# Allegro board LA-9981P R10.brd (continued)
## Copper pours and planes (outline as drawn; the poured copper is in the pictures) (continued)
DH_CHG on TOP (solid shape): 152.62,169.75 152.62,168.79 152.49,168.67 151.48,168.67 151.29,168.86 151.29,169.81 151.41,169.94 152.43,169.94
DH_CHG on TOP (solid shape): 166.78,169.43 166.78,169.37 166.72,169.3 165.76,169.3 165.57,169.11 164.56,169.11 164.49,169.17 164.49,169.49 164.56,169.56 166.65,169.56
DH_CHG on IN1 (solid shape): 147.01,169.55 147.01,168.72 146.95,168.66 145.04,168.66 144.92,168.79 144.92,169.55 145.11,169.74 146.82,169.74
DH_CHG on IN1 (solid shape): 153.13,169.68 153.13,168.86 152.94,168.67 150.27,168.67 150.08,168.86 150.08,169.62 150.33,169.87 152.94,169.87
DH_CHG on IN1 (solid shape): 164.49,169.68 165.26,169.68 165.51,169.43 165.51,169.17 165.38,169.05 163.67,169.05 163.35,169.37 163.35,170 163.48,170.13 164.05,170.13
DL_1.35V on BOTTOM (solid shape): 157.58,12.72 157.58,11.83 157.45,11.71 156.56,11.71 156.44,11.83 156.44,12.66 156.56,12.79 157.52,12.79
DL_1.35V on BOTTOM (solid shape): 157.83,23.7 157.83,22.76 157.71,22.63 157.71,21.61 157.63,21.54 157.22,21.54 157.09,21.66 157.09,22.46 157.58,22.95 157.58,23.7 157.64,23.76 157.77,23.76
DL_1.35V on IN3 (solid shape): 157.58,12.98 157.58,11.77 157.48,11.67 156.53,11.67 156.44,11.77 156.44,13.04 156.63,13.23 157.32,13.23
DL_1.35V on IN3 (solid shape): 157.71,22.57 157.71,21.61 158.02,21.3 158.02,19.71 157.9,19.58 157.2,19.58 156.94,19.84 156.94,21.36 157.2,21.61 157.2,22.5 157.39,22.69 157.58,22.69
DL_CHG on TOP (solid shape): 161.83,175.52 161.83,174.89 161.57,174.64 160.18,174.64 159.99,174.45 159.16,174.45 158.97,174.64 158.97,175.46 159.16,175.65 161.7,175.65
DL_CHG on TOP (solid shape): 166.72,173.24 166.72,171.97 167.1,171.59 167.1,170.7 167.03,170.64 166.91,170.64 166.84,170.7 166.84,170.76 165.64,171.97 165.64,173.18 165.95,173.49 166.46,173.49
EN_PCIE on BOTTOM (solid shape): 197.23,66.3 197.23,65.75 197.48,65.5 198.16,65.5 198.26,65.4 198.26,64.76 198.17,64.67 196.55,64.67 196.16,65.07 195.57,65.07 195.51,65.13 195.51,66.23 195.67,66.39 197.15,66.39
ERP_LOT6 on TOP (solid shape): 129.07,174.15 129.07,172.9 129.88,172.09 129.88,170.78 129.81,170.71 129.27,170.71 129.22,170.77 129.22,172.13 128.67,172.68 128.67,174.17 128.76,174.26 128.97,174.26
GPU_B+ on TOP (solid shape): 214.26,79.73 214.26,74.86 213.64,74.24 213.64,64.78 213.07,64.21 207.62,64.21 207.62,64.22 207.35,64.22 207.27,64.3 207.27,76.05 211.2,79.98 214.02,79.98
INT-SPK-L+ on TOP (solid shape): 63.47,25.28 63.47,24.52 63.34,24.39 60.61,24.39 60.48,24.52 60.48,25.22 60.67,25.41 63.34,25.41
INT-SPK-L+ on TOP (solid shape): 27.08,16.01 27.08,15.82 26.38,15.12 26.19,15.12 26.06,15.25 26.06,15.63 26.64,16.2 26.89,16.2
INT-SPK-L+ on IN1 (solid shape): 62.7,25.03 62.7,24.39 62.45,24.14 60.42,24.14 60.23,24.33 60.23,25.16 60.29,25.22 62.51,25.22
INT-SPK-L+ on IN1 (solid shape): 27.97,17.54 27.97,16.65 26.44,15.12 26.25,15.12 26.06,15.31 26.06,15.63 26.83,16.39 26.83,16.44 26.84,16.45 26.92,16.69 26.83,16.92 26.83,17.28 27.14,17.6 27.91,17.6
INT-SPK-L- on TOP (solid shape): 63.47,24.08 63.47,23.25 63.4,23.19 60.73,23.19 60.48,23.44 60.48,24.01 60.73,24.27 63.27,24.27
INT-SPK-L- on TOP (solid shape): 27.45,15.96 27.45,15.3 26.89,14.74 26.7,14.74 26.57,14.87 26.57,15.11 26.61,15.16 26.94,15.5 26.97,15.52 27.14,15.7 27.14,15.71 27.21,15.77 27.21,15.95 27.27,16.01 27.4,16.01
INT-SPK-L- on IN1 (solid shape): 62.64,23.82 62.64,23.12 62.51,23 60.67,23 60.48,23.19 60.48,23.82 60.67,24.01 62.45,24.01
INT-SPK-L- on IN1 (solid shape): 29.49,16.77 29.49,16.2 29.21,15.92 29.13,15.89 29.05,15.94 28.7,16.11 28.41,15.86 28.4,15.82 28.35,15.82 27.88,15.35 27.86,15.35 27.58,15.25 27.48,14.97 27.48,14.95 27.14,14.62 26.76,14.62 26.57,14.81 26.57,15.06 28.67,17.15 29.11,17.15
INT-SPK-R+ on TOP (solid shape): 64.42,22.36 64.42,21.54 64.35,21.47 62,21.47 61.81,21.66 61.81,22.3 62,22.49 64.29,22.49
INT-SPK-R+ on IN1 (solid shape): 30.25,15.12 30.25,14.36 30.06,14.17 28.86,14.17 28.29,14.74 28.29,15.25 28.35,15.31 30.06,15.31
INT-SPK-R+ on IN1 (solid shape): 63.53,22.17 63.53,21.54 63.34,21.35 59.85,21.35 59.72,21.47 59.72,22.24 59.91,22.43 63.27,22.43
INT-SPK-R- on TOP (solid shape): 64.42,21.09 64.42,20.27 64.35,20.2 61.88,20.2 61.75,20.33 61.75,21.09 61.88,21.22 64.29,21.22
INT-SPK-R- on IN1 (solid shape): 63.53,21.16 63.53,20.33 63.4,20.2 59.91,20.2 59.72,20.39 59.72,20.97 59.97,21.22 63.47,21.22
INT-SPK-R- on IN1 (solid shape): 28.13,15.09 28.13,15.06 28.12,14.95 28.15,14.85 28.16,14.84 28.16,14.62 28.73,14.04 28.73,13.54 28.67,13.47 27.84,13.47 27.52,13.79 27.52,14.82 27.9,15.19 28.03,15.19
LDO_3V on BOTTOM (solid shape): 147.35,155.2 146.69,155.2 146.64,155.25 146.01,155.25 145.96,155.3 145.39,155.3 145.34,155.35 145.34,155.5 145.39,155.55 146,155.55 146.21,155.77 146.38,155.77 146.69,156.09 147.35,156.09
LG_3V on TOP (solid shape): 130.84,22.71 130.84,21.73 130.58,21.47 129.89,21.47 129.7,21.66 129.7,22.71 129.89,22.9 130.65,22.9
LG_3V on TOP (solid shape): 130,19.37 130,19.07 129.65,18.72 129.64,18.72 128.74,17.82 128.74,17.19 128.68,17.12 128.62,17.12 128.55,17.19 128.55,18.48 129.57,19.5 129.87,19.5
LG_5V on TOP (solid shape): 125.57,25.57 125.57,25.19 125.06,24.68 124.3,24.68 124.17,24.81 124.17,25 124.43,25.25 124.43,25.57 124.62,25.76 125.38,25.76
LG_5V on TOP (solid shape): 126.01,19.04 126.03,19.04 126.05,19.02 126.09,18.98 126.15,18.95 126.93,18.18 126.94,18.19 127.04,18.19 127.16,18.07 127.16,17.25 127.03,17.12 126.97,17.12 126.9,17.19 126.9,17.57 126.51,17.96 126.18,17.96 125.63,18.51 125.63,18.94 125.73,19.04
LG_5V on IN3 (solid shape): 126.63,18.39 126.63,17.99 126.49,17.85 126.2,17.85 124.99,19.06 124.99,19.27 125.37,19.65
LG_5V on IN3 (solid shape): 125.7,25.57 125.7,24.7 125.02,24.02 124.37,24.02 124.11,24.28 124.11,25.63 124.23,25.76 125.5,25.76
LG_+1.2VSP on BOTTOM (solid shape): 180.88,172.79 180.88,172.1 180.69,171.91 179.8,171.91 179.67,172.03 179.67,172.86 179.8,172.98 180.69,172.98
LG_+1.2VSP on IN3 (solid shape): 180.81,172.98 180.81,172.03 180.69,171.91 179.92,171.91 179.73,172.1 179.73,172.92 179.86,173.05 180.75,173.05
LG_+1.2VSP on IN3 (solid shape): 185.83,174.32 185.83,173.68 185.7,173.56 184.81,173.56 184.69,173.68 184.69,174.7 184.81,174.83 185.32,174.83
LX_1.05V on BOTTOM (solid shape): 147.67,159.01 147.67,157.74 147.55,157.61 146.66,157.61 146.53,157.74 146.53,159.01 146.66,159.13 147.55,159.13
LX_1.05V on BOTTOM (solid shape): 144.59,152.94 144.99,152.53 145.32,152.53 145.89,151.96 145.89,148.02 145.39,147.51 142.32,147.51 140.74,145.93 138.85,145.93 138.72,146.06 138.72,147.02 139.09,147.39 139.79,147.39 141.07,148.67 141.07,150.62 143.42,152.97 143.42,154.17 144.59,154.17
LX_1.5VSP on BOTTOM (solid shape): 110.12,29 110.12,26.97 109.99,26.84 109.99,26.08 109.93,26.01 109.8,26.01 109.74,26.08 109.74,26.78 109.55,26.97 108.85,26.97 108.66,26.78 108.66,26.52 108.02,26.52 108.02,27.41 107.77,27.66 105.77,27.66 105.35,28.08 105.35,29.76 105.61,30.01 109.1,30.01
LX_1.8VSP on BOTTOM (solid shape): 221.58,95.2 221.58,94.05 221.39,93.86 219.93,93.86 219.17,93.1 219.17,92.09 219.04,91.96 218.98,91.96 218.91,92.02 218.91,93.04 218.09,93.86 217.26,93.86 216.5,94.63 215.67,94.63 215.61,94.69 215.61,95.39 215.67,95.45 221.33,95.45
LX_3V on TOP (solid shape): 135.79,27.89 135.79,23.63 135.47,23.32 134.14,23.32 133.63,22.81 133.63,22.58 133.51,22.46 131.41,22.46 131.22,22.65 131.22,24.9 131.54,25.22 132.11,25.22 132.62,25.73 132.62,27.95 132.81,28.14 135.54,28.14
LX_3V on TOP (solid shape): 131.16,16.23 131.66,16.23 131.85,16.04 131.85,15.53 131.79,15.47 131.22,15.47 130.84,15.85 130.01,15.85 129.82,16.04 128.87,16.04 128.81,16.11 128.81,16.17 128.87,16.23 130.01,16.23 130.14,16.36 131.03,16.36
LX_3V on BOTTOM (solid shape): 135.79,27.73 135.79,23.47 135.41,23.09 130.52,23.09 130.33,23.28 130.33,27.73 130.58,27.98 135.54,27.98
LX_3V on IN1 (solid shape): 134.97,24.14 134.97,22.93 134.78,22.74 134.14,22.74 133.95,22.93 133.95,24.14 134.01,24.2 134.9,24.2
LX_3V on IN1 (solid shape): 131.92,16.71 131.92,16.42 131.35,15.85 130.14,15.85 130.01,15.98 130.01,16.33 130.36,16.68 131.09,16.68 131.38,16.97 131.66,16.97
LX_5V on TOP (solid shape): 125.66,16.2 126.58,16.2 126.65,16.14 126.65,16.03 126.58,15.96 125.55,15.96 125.44,15.85 124.65,15.85 124.43,16.08 123.89,16.08 123.77,16.2 123.77,16.69 123.85,16.77 125.09,16.77
LX_5V on TOP (solid shape): 122.27,28.74 122.27,27.25 122.2,27.19 120.78,27.19 120.49,26.9 120.49,25.88 120.68,25.69 121.95,25.69 122.54,25.11 123.58,25.11 123.66,25.03 123.66,22.65 123.47,22.46 121.25,22.46 121.12,22.58 121.12,23.09 120.87,23.34 119.22,23.34 119.03,23.54 119.03,28.62 119.35,28.93 122.08,28.93
LX_5V on BOTTOM (solid shape): outline of 85 points within 119.2,23.47 124.3,28.36
LX_5V on IN1 (solid shape): 125.7,16.61 125.7,15.79 125.5,15.6 123.41,15.6 123.16,15.85 123.16,16.74 123.28,16.87 125.44,16.87
LX_5V on IN1 (solid shape): 120.49,24.08 120.49,23.76 120.3,23.57 120.3,22.93 119.54,22.93 119.54,23.57 119.35,23.76 119.35,24.08 119.47,24.2 120.36,24.2
LX_CHG on TOP (solid shape): 166.78,168.98 166.78,168.86 166.72,168.79 165.76,168.79 164.87,167.9 163.6,167.9 163.54,167.97 163.54,168.73 163.6,168.79 164.56,168.79 164.68,168.92 165.57,168.92 165.7,169.05 166.72,169.05
LX_CHG on TOP (solid shape): 154.44,176.75 154.44,175.61 154.98,175.07 158.05,175.07 158.08,175.03 158.08,170.89 158.02,170.83 156.87,170.83 156.43,170.38 156.43,168.86 156.24,168.67 154.33,168.67 154.14,168.48 154.14,168.16 154.02,168.03 153.25,168.03 153.06,168.22 153.06,169.87 152.62,170.32 151.22,170.32 150.84,169.94 150.84,168.79 150.62,168.57 147.06,168.57 146.89,168.74 146.89,170.87 148.9,172.89 149.35,172.89 153.32,176.86 154.33,176.86
LX_CHG on BOTTOM (solid shape): 157.51,174.45 157.51,168.6 156.81,167.9 153.06,167.9 152.75,168.22 152.75,169.75 152.3,170.19 149.06,170.19 148.75,170.51 148.75,172.98 150.52,174.76 157.19,174.76
LX_CHG on IN1 (solid shape): 155.67,168.73 155.67,168.03 155.48,167.84 153.25,167.84 153.06,168.03 153.06,168.54 153.38,168.86 155.54,168.86
LX_CHG on IN1 (solid shape): 165.51,168.79 165.51,168.41 164.94,167.84 163.48,167.84 163.29,168.03 163.29,168.67 163.48,168.86 164.56,168.86 164.62,168.92 165.38,168.92
LX_PCIE on TOP (solid shape): 197.77,69.42 197.77,67.89 197.6,67.72 195.72,67.72 195.41,67.42 195.41,64.94 195.27,64.79 193.09,64.79 193.09,64.79 192.77,65.11 192.77,69.45 192.91,69.59 197.6,69.59
LX_PCIE on BOTTOM (solid shape): 197.85,69.83 197.85,67.06 197.6,66.81 195.53,66.81 194.81,66.08 194.81,65.19 194.72,65.11 193.08,65.11 192.84,65.35 192.84,69.88 193.24,70.29 197.39,70.29
LX_VDDCI on BOTTOM (solid shape): 185.89,184.1 185.89,175.91 185.77,175.78 184.5,175.78 184.12,176.16 184.12,177.37 182.16,179.32 182.16,180.4 181.19,181.37 179.86,181.37 179.73,181.49 179.73,182.45 179.8,182.51 181,182.51 183.23,184.73 185.26,184.73
MIC_IN on TOP (solid shape): 16.16,23.63 16.16,21.28 16.09,21.22 15.08,21.22 15.01,21.28 15.01,23.44 15.27,23.7 16.09,23.7
MIC_IN on TOP (solid shape): 27.52,25.28 27.52,24.46 27.4,24.33 27.4,23.19 27.33,23.12 27.21,23.12 27.14,23.19 27.14,24.27 27.02,24.39 27.02,24.65 27.14,24.78 27.14,25.22 27.27,25.35 27.46,25.35
MIC_IN on BOTTOM (solid shape): 16.48,22.49 16.48,21.85 16.41,21.79 15.27,21.79 15.01,22.05 15.01,22.87 15.08,22.93 16.03,22.93
MIC_IN on IN1 (solid shape): 16.03,24.14 16.03,22.68 15.9,22.55 15.14,22.55 15.01,22.68 15.01,24.08 15.21,24.27 15.9,24.27
MIC_IN on IN1 (solid shape): 27.52,25.22 27.52,24.46 27.33,24.27 26.06,24.27 25.94,24.39 25.94,25.22 26.13,25.41 27.33,25.41
MIC_IN_R on TOP (solid shape): 16.22,20.71 16.22,19.7 16.4,19.51 16.4,17.86 16.59,17.67 16.59,16.26 16.12,15.78 15.19,15.78 14.95,16.01 14.95,17.66 15.59,18.3 15.59,19.51 15.4,19.7 15.08,19.7 14.95,19.82 14.95,20.71 15.08,20.84 16.09,20.84
MIC_IN_R on IN3 (solid shape): 16.73,17.66 16.73,16.9 16.54,16.71 15.14,16.71 14.89,16.97 14.89,17.6 15.14,17.85 16.54,17.85
PCIE_B+ on BOTTOM (solid shape): 194.85,62.81 194.85,61.99 195.67,61.16 195.67,58.68 195.56,58.57 193.69,58.57 193.58,58.68 193.58,59.07 194.02,59.51 194.02,61.54 193.51,62.05 193.51,62.88 193.58,62.94 194.72,62.94
PSID on BOTTOM (solid shape): 138.38,183.06 138.38,178.15 138.11,177.89 135.72,177.89 135.36,178.24 135.36,183.19 135.46,183.29 138.15,183.29
REGN on TOP (solid shape): 165.19,172.92 165.19,171.52 166.14,170.57 166.65,170.57 166.78,170.44 166.78,170.38 166.65,170.25 165.76,170.25 165.51,170.51 164.3,170.51 164.18,170.64 164.18,171.46 164.37,171.65 164.37,173.05 164.43,173.11 165,173.11
RING2 on TOP (solid shape): 17.81,23.44 17.81,21.47 17.62,21.28 16.54,21.28 16.48,21.35 16.48,23.57 16.6,23.7 17.55,23.7
RING2 on TOP (solid shape): 28.22,25.28 28.22,24.39 28.16,24.33 28.03,24.33 27.84,24.14 27.84,23.19 27.78,23.12 27.65,23.12 27.59,23.19 27.59,24.2 27.78,24.39 27.78,25.28 27.84,25.35 28.16,25.35
RING2 on IN3 (solid shape): 17.68,23.76 17.68,22.62 17.55,22.49 16.86,22.49 16.6,22.74 16.6,23.82 16.79,24.01 17.43,24.01
RING2 on IN3 (solid shape): 28.29,26.24 28.29,24.33 28.16,24.2 27.84,24.2 27.71,24.33 27.71,25.35 27.59,25.47 26.89,25.47 26.83,25.54 26.83,26.17 27.08,26.43 28.1,26.43
RING2_R on TOP (solid shape): 17.68,20.71 17.68,19.77 17.48,19.57 17.48,18.43 18.28,17.64 18.28,15.4 18.04,15.16 17.06,15.16 16.89,15.34 16.89,17.95 16.66,18.17 16.66,19.7 16.54,19.82 16.54,20.71 16.6,20.78 17.61,20.78
RING2_R on IN3 (solid shape): 18.08,15.46 18.08,13.94 17.88,13.75 17.06,13.75 16.81,14 16.81,15.4 17.12,15.71 17.82,15.71
SNB_1.05V on BOTTOM (solid shape): 139.67,149.99 139.93,149.74 140.37,149.74 140.37,148.72 138.72,148.72 138.65,148.79 138.65,150.68 138.78,150.81 139.67,150.81
SNB_VDDCI on BOTTOM (solid shape): 183.04,177.56 183.04,175.84 182.97,175.78 180.75,175.78 180.62,175.91 180.62,176.54 180.69,176.6 181.7,176.6 181.83,176.73 181.83,177.56 181.89,177.62 182.97,177.62
SNUB_PCIE on TOP (solid shape): 197.96,66.74 197.96,64.81 197.85,64.7 196.86,64.7 196.78,64.79 196.78,65.5 196.71,65.57 195.96,65.57 195.75,65.77 195.75,66.83 195.87,66.96 197.74,66.96
SW_1.35V on TOP (solid shape): 154.66,16.85 154.66,15.64 154.72,15.58 154.72,15.33 154.59,15.2 153.77,15.2 153.58,15.39 153.58,16.79 153.77,16.98 154.53,16.98
SW_1.35V on TOP (solid shape): 157.39,23.65 157.39,23.39 156.37,22.38 156.05,22.38 155.74,22.69 155.74,23.14 156.44,23.84 157.2,23.84
SW_1.35V on BOTTOM (solid shape): 157.39,24.08 157.39,23.39 156.82,22.82 156.82,21.36 156.56,21.11 156.05,21.11 155.93,21.23 155.93,23.33 156.47,23.87 156.47,24.06 156.56,24.15 157.32,24.15
SW_1.35V on BOTTOM (solid shape): 155.16,17.73 155.16,15.32 155.93,14.55 155.93,11.69 156.05,11.57 156.56,11.57 156.68,11.44 156.68,10.93 156.62,10.87 154.1,10.87 152.37,12.6 150.34,12.6 149.96,12.98 149.96,16.6 150.72,17.36 153.07,17.36 153.5,17.79 153.51,17.79 153.57,17.85 155.03,17.85
SW_+1.2VSP on TOP (solid shape): 176.88,172.73 176.88,171.46 177.07,171.27 177.59,171.27 178.2,171.27 179.42,171.27 179.48,171.21 179.48,170.37 179.38,170.27 179.09,170.27 178.84,170.03 178.84,167.82 178.68,167.65 175.67,167.65 175.1,168.22 175.1,172.67 175.23,172.79 176.81,172.79
SW_+1.2VSP on TOP (solid shape): 185.7,172.35 185.7,172.22 185.64,172.16 184.81,172.16 184.69,172.03 184.44,172.03 184.38,171.97 184.37,171.97 184.12,171.72 183.87,171.72 183.8,171.71 183.67,171.59 183.67,171.4 183.54,171.27 182.72,171.27 182.65,171.33 182.65,171.91 183.16,172.41 185.64,172.41
SW_+1.2VSP on BOTTOM (solid shape): 179.42,175.02 179.42,168.03 179.1,167.71 175.16,167.71 174.78,168.1 174.78,172.22 177.66,172.22 177.67,172.16 177.68,172.11 177.7,172.06 177.73,172.02 177.77,171.96 177.77,171.93 177.77,171.9 177.73,171.84 177.7,171.8 177.68,171.75 177.67,171.7 177.66,171.64 177.67,171.59 177.68,171.54 177.7,171.49 177.72,171.44 177.76,171.4 177.8,171.36 177.84,171.33 177.89,171.31 177.94,171.29 177.99,171.28 178.05,171.28 178.1,171.29 178.15,171.31 178.2,171.33 178.24,171.36 178.28,171.4 178.32,171.44 178.34,171.49 178.36,171.54 178.37,171.59 178.38,171.64 178.37,171.7 178.36,171.75 178.34,171.8 178.31,171.84 178.27,171.9 178.27,171.93 178.27,171.96 178.31,172.02 178.34,172.06 178.36,172.11 178.37,172.16 178.38,172.22 178.37,172.27 178.36,172.32 178.34,172.37 178.32,172.42 178.28,172.46 178.24,172.5 178.2,172.53 178.15,172.55 178.1,172.57 178.05,172.58 177.99,172.58 177.94,172.57 177.89,172.55 177.84,172.53 177.8,172.5 177.76,172.46 177.72,172.42 177.7,172.37 177.68,172.32 177.67,172.27 177.66,172.22 174.78,172.22 174.78,175.21 174.97,175.4 179.04,175.4
SW_+1.2VSP on IN1 (solid shape): 179.73,171.02 180.56,171.02 180.69,170.89 180.69,170.44 180.5,170.25 179.23,170.25 179.04,170.44 179.04,171.14 179.23,171.33 179.42,171.33
SW_+1.2VSP on IN1 (solid shape): 184.75,172.35 184.75,172.1 184.63,171.97 184.6,171.98 184.53,171.98 184.45,171.97 184.13,171.97 183.99,171.97 183.35,171.33 182.91,171.33 182.78,171.46 182.78,171.84 183.42,172.48 184.62,172.48
SW_CPU2 on BOTTOM (solid shape): 112.36,143.19 112.36,140.71 112.34,140.7 110.93,140.7 110.65,140.41 110.65,139.2 110.46,139.01 109.38,139.01 109.19,138.82 109.19,138.19 109.12,138.12 106.26,138.12 106.2,138.19 106.2,139.52 106.39,139.71 108.3,139.71 108.42,139.84 108.42,140.54 108.36,140.6 106.52,140.6 106.14,140.98 106.14,142.82 106.65,143.33 112.22,143.33
SW_VGA_CORE on TOP (solid shape): 206.66,76.97 206.66,76.12 206.4,75.87 206.4,72.76 206.11,72.46 203.48,72.46 203.17,72.15 203.17,70.69 203.42,70.43 206.08,70.43 206.47,70.05 206.47,66.94 206.46,66.94 206.46,66.74 206.25,66.53 203.32,66.53 202.09,67.77 202.09,77.16 202.25,77.32 206.31,77.32
SW_VGA_CORE on BOTTOM (solid shape): 204.56,61.86 204.56,60.8 204.49,60.58 204.56,60.36 204.56,60.08 204.69,59.95 204.69,58.88 204.63,58.81 204.56,58.81 204.44,58.94 204.44,59.88 204.44,59.89 204.24,60.08 204.18,60.08 204.05,60.21 204.05,60.9 204.05,61.03 203.86,61.22 203.55,61.22 203.48,61.29 203.48,62.05 203.55,62.11 204.31,62.11
SW_VGA_CORE on BOTTOM (solid shape): outline of 156 points within 202.09,61.16 213.72,76.99
SW_VGA_CORE on IN1 (solid shape): 205.45,62.75 205.45,62.43 204.63,61.61 204.63,60.21 204.44,60.02 204.12,60.02 204.05,60.08 204.05,62.69 204.31,62.94 205.26,62.94
SW_VGA_CORE on IN1 (solid shape): 206.85,77.04 206.85,75.89 206.28,75.32 206.28,66.94 206.02,66.69 203.36,66.69 202.97,67.07 202.97,70.31 203.1,70.43 205.2,70.43 205.39,70.62 205.39,72.08 205.07,72.4 202.34,72.4 202.09,72.65 202.09,76.46 203.1,77.48 206.4,77.48
SW_VGA_CORE on IN2 (solid shape): 206.85,77.04 206.85,75.89 206.28,75.32 206.28,66.94 206.02,66.69 203.23,66.69 202.97,66.94 202.97,70.24 203.17,70.43 205.2,70.43 205.39,70.62 205.39,72.08 205.07,72.4 202.28,72.4 202.09,72.59 202.09,76.46 203.1,77.48 206.4,77.48
SW_VGA_CORE on IN3 (solid shape): 206.85,77.04 206.85,75.89 206.28,75.32 206.28,66.94 206.02,66.69 203.17,66.69 202.85,67 202.85,70.18 203.1,70.43 205.2,70.43 205.39,70.62 205.39,72.08 205.07,72.4 202.34,72.4 202.09,72.65 202.09,76.46 203.1,77.48 206.4,77.48
UG_3V on TOP (solid shape): 133.7,29.22 133.7,28.52 133.51,28.33 132.74,28.33 132.55,28.52 132.55,29.25 132.65,29.35 133.57,29.35
UG_3V on TOP (solid shape): 130.2,18.07 130.2,17.82 129.82,17.44 129.82,16.93 129.76,16.87 128.87,16.87 128.87,16.99 128.87,17.13 128.87,17.57 129.66,18.35 129.92,18.35
UG_3V on IN1 (solid shape): 131.09,18.66 131.09,18.54 129.68,17.12 129.07,17.12 128.93,17.26 128.93,17.53 130.5,19.09 130.66,19.09
UG_3V on IN1 (solid shape): 133.66,29.25 133.66,27.86 133.47,27.66 132.84,27.66 132.59,27.92 132.59,29.25 132.71,29.38 133.54,29.38
UG_5V on TOP (solid shape): 126.77,17.44 126.77,16.9 126.65,16.77 125.89,16.77 125.44,17.22 125.44,17.54 125.62,17.71 126.5,17.71
UG_5V on TOP (solid shape): 122.33,26.87 122.33,26.05 122.11,25.82 120.74,25.82 120.62,25.95 120.62,26.84 120.74,26.96 122.24,26.96
UG_5V on IN1 (solid shape): 125.76,17.69 126.65,17.69 126.71,17.63 126.71,17.31 126.46,17.06 124.81,17.06 124.64,17.22 124.64,17.66 124.88,17.9 125.55,17.9
UG_5V on IN1 (solid shape): 121.31,26.9 121.31,26.08 121.89,25.5 121.89,25.25 121.76,25.12 121.19,25.12 120.49,25.82 120.49,26.9 120.62,27.03 121.19,27.03
UG_+1.2VSP on TOP (solid shape): 178.27,172.35 178.27,171.52 178.15,171.4 177.64,171.4 177.13,171.91 177.13,172.6 177.26,172.73 177.89,172.73
UG_+1.2VSP on TOP (solid shape): 185.77,171.84 185.77,171.71 185.64,171.59 184.88,171.59 184.37,171.08 183.99,171.08 183.8,171.27 183.8,171.46 183.92,171.59 184.18,171.59 184.46,171.87 184.48,171.87 184.57,171.87 184.65,171.9 184.66,171.91 185.7,171.91
UG_+1.2VSP on IN1 (solid shape): 178.46,172.48 178.46,170.76 178.34,170.64 177.7,170.64 177.57,170.76 177.57,172.41 177.77,172.6 178.34,172.6
UG_+1.2VSP on IN1 (solid shape): 184.75,171.78 184.75,171.02 183.8,170.06 183.54,170.06 183.26,170.35 183.26,170.92 184.18,171.84 184.69,171.84
UG_VGA_CORE on TOP (solid shape): 206.4,71.64 206.4,71.45 206.21,71.26 203.8,71.26 203.67,71.38 203.67,71.83 203.8,71.96 206.09,71.96
UG_VGA_CORE on TOP (solid shape): 206.4,65.91 206.4,65.47 206.21,65.28 204.05,65.28 203.8,65.53 203.8,65.97 203.99,66.16 206.15,66.16
UG_VGA_CORE on BOTTOM (solid shape): 203.93,60.84 203.93,60.15 204.18,59.89 204.24,59.89 204.31,59.83 204.31,58.88 204.24,58.81 204.12,58.81 204.05,58.88 204.05,59.07 203.1,60.02 203.1,60.72 203.36,60.97 203.8,60.97
UG_VGA_CORE on IN1 (solid shape): 204.94,71.77 204.94,71.13 204.69,70.88 202.85,70.88 202.47,70.5 202.47,66.88 203.04,66.3 204.75,66.3 205.01,66.05 205.01,65.22 204.82,65.03 204.18,65.03 203.86,64.72 203.86,59.98 203.78,59.9 203.1,59.9 202.78,60.21 202.78,64.34 201.39,65.73 201.39,71.38 201.96,71.96 204.75,71.96
VCIN1_PH on TOP (solid shape): 130.31,181.93 130.31,178.13 130.21,178.03 129.77,178.03 129.61,178.19 129.61,181.97 129.66,182.01 130.22,182.01
N16988653 on BOTTOM (solid shape): 215.65,91.9 215.65,90.87 216.07,90.45 217.77,90.45 218.02,90.21 218.02,89.04 217.85,88.87 215.47,88.87 214.89,89.45 214.89,92 214.92,92.03 215.52,92.03
N16988706 on BOTTOM (solid shape): 216.56,94.05 216.56,93.36 216.94,92.97 216.94,92.4 216.88,92.34 216.37,92.34 215.6,93.12 215.6,94.05 215.66,94.12 216.5,94.12
N17002625 on BOTTOM (solid shape): 177.51,186.76 177.51,186.19 177.45,186.13 175.42,186.13 175.29,186.26 175.29,186.83 175.35,186.89 177.38,186.89
N17045846 on BOTTOM (solid shape): 202.85,62.11 202.85,61.29 202.72,61.16 200.94,61.16 200.88,61.22 200.88,61.8 200.94,61.86 201.64,61.86 201.96,62.18 202.78,62.18
N17046121 on BOTTOM (solid shape): 215.29,62.05 215.29,61.16 215.17,61.03 213.71,61.03 213.45,61.29 213.45,61.99 213.64,62.18 215.17,62.18
N17046121 on BOTTOM (solid shape): 215.61,67.89 215.61,67.13 215.42,66.94 213.77,66.94 213.52,67.19 213.52,67.64 213.67,67.8 214.56,67.8 214.79,68.02 215.48,68.02
N17046121 on BOTTOM (solid shape): 205.64,60.97 205.64,60.21 205.51,60.08 205.51,58.88 205.45,58.81 205.32,58.81 205.26,58.88 205.26,60.08 205.13,60.21 205.13,60.37 205.14,60.39 205.2,60.58 205.13,60.78 205.13,60.97 205.26,61.1 205.51,61.1
N17046121 on IN3 (solid shape): 207.04,61.1 207.04,60.46 206.66,60.08 205.26,60.08 205.13,60.21 205.13,60.37 205.14,60.39 205.2,60.58 205.14,60.77 205.13,60.78 205.13,60.91 205.32,61.1 206.4,61.1 206.66,61.35 206.78,61.35
N17046121 on IN3 (solid shape): 215.55,67.96 215.55,67.07 215.42,66.94 214.79,66.94 214.72,66.88 214.72,62.43 214.98,62.18 215.29,62.18 215.36,62.11 215.36,61.22 215.23,61.1 212.56,61.1 212.18,61.48 212.18,62.05 212.44,62.3 213.13,62.3 213.45,62.62 213.45,67.77 213.71,68.02 215.48,68.02
N17608587 on BOTTOM (solid shape): 149.38,158.22 149.38,157.29 148.95,156.86 148.95,156.6 148.75,156.4 148.12,156.4 148.12,158.56 149.04,158.56
N18009264 on BOTTOM (solid shape): 148.05,164.92 148.05,161.36 147.54,160.86 142.71,160.86 142.65,160.92 142.65,161.68 142.78,161.81 144.3,161.81 144.55,162.06 144.55,162.44 144.43,162.57 142.71,162.57 142.59,162.7 142.59,163.27 142.65,163.33 144.75,163.33 145.38,163.97 145.38,164.79 145.7,165.11 147.86,165.11
N18009411 on BOTTOM (solid shape): 148.05,183.83 148.05,182.63 147.79,182.37 146.41,182.37 146.21,182.57 146.21,182.83 146.4,183.02 146.9,183.02 147.03,183.14 147.03,184.16 147.16,184.29 147.6,184.29
N18009417 on TOP (solid shape): 157,177.77 157,176.18 156.87,176.06 154.91,176.06 154.71,176.25 154.71,176.76 154.78,176.82 155.48,176.82 155.73,177.07 155.73,177.77 155.86,177.9 156.87,177.9
N18284053 on BOTTOM (solid shape): 138.15,176.66 138.15,174.13 137.91,173.89 135.94,173.89 135.41,173.36 135.41,170.13 137.95,167.59 137.95,165.56 137.81,165.41 135.33,165.41 135.03,165.71 135.03,165.9 133.03,167.9 133.03,174.35 135.63,176.95 137.87,176.95
N19792312 on BOTTOM (solid shape): 24.27,27.21 24.27,26.33 24.13,26.18 22.56,26.18 22.51,26.23 22.51,26.88 22.95,27.32 24.17,27.32
N21178712 on TOP (solid shape): 132.14,174.01 132.14,172.45 132.04,172.36 129.89,172.36 129.27,172.97 129.27,174.2 129.35,174.28 131.87,174.28
N32320781 on BOTTOM (solid shape): 140.81,165.34 140.81,164.41 141.7,163.52 141.7,162.63 141.63,162.57 140.11,162.57 139.86,162.32 139.86,162 140.11,161.75 141.57,161.75 141.7,161.62 141.7,161.17 141.44,160.92 138.71,160.92 138.27,161.36 138.27,164.92 138.71,165.36 140.78,165.36
N46608740 on BOTTOM (solid shape): 142.33,167.02 143.09,167.02 143.22,166.89 143.22,165.43 143.16,165.36 142.27,165.36 142.08,165.56 138.59,165.56 138.27,165.87 138.27,167.27 138.46,167.46 141.89,167.46
N46660696 on TOP (solid shape): 109.12,144.03 109.12,142.57 108.87,142.31 107.98,142.31 107.85,142.44 107.85,143.2 107.66,143.39 107.03,143.39 106.9,143.52 106.9,144.03 107.03,144.16 108.99,144.16
N47008006 on TOP (solid shape): 129.18,177.77 129.18,176.3 129.08,176.2 129.08,174.62 128.98,174.51 128.1,174.51 128,174.62 128,177.75 128.16,177.91 129.04,177.91
N47008301 on TOP (solid shape): 129.44,179.52 129.44,178.45 129.27,178.28 127.98,178.28 127.75,178.51 127.75,179.68 127.92,179.85 129.12,179.85
N47305899 on TOP (solid shape): 211.74,63.45 211.74,61.86 211.67,61.8 210.15,61.8 209.58,62.37 209.58,63.32 209.77,63.51 211.67,63.51
N47415258 on TOP (solid shape): 135.79,21.63 134.7,20.54 132.56,20.54 132.3,20.8 132.3,21.76 132.43,21.88 133.63,21.88 134.14,22.39 134.14,22.71 135.79,22.71
N47415272 on TOP (solid shape): 120.87,22.84 120.87,22.2 120.92,22.16 121.9,22.16 122.01,22.05 122.01,20.93 121.89,20.8 119.73,20.8 119.15,21.38 119.15,22.9 120.81,22.9
N47417471 on BOTTOM (solid shape): 109.99,24.55 109.99,23.79 110.12,23.66 110.12,21.07 109.76,20.71 109.12,20.71 108.99,20.84 108.99,21.28 107.6,21.28 107.6,20.78 107.53,20.71 107.03,20.71 106.45,21.28 106.45,23.44 106.99,23.98 108.79,23.98 109.1,23.66 109.61,23.66 109.74,23.79 109.74,24.55 109.8,24.62 109.93,24.62
N47420895 on BOTTOM (solid shape): 161.83,11.5 161.83,9.92 161.76,9.85 160.62,9.85 159.73,10.74 157.06,10.74 156.94,10.87 156.94,11.38 157.06,11.5 160.62,11.5 160.68,11.57 161.76,11.57
N64564173 on TOP (solid shape): 183.61,170.57 183.61,170 184.05,169.56 184.05,168.73 183.99,168.67 183.35,168.67 183.23,168.79 183.23,169.37 182.72,169.87 182.72,170.57 182.78,170.64 183.54,170.64
N64564191 on TOP (solid shape): 180.75,171.33 180.75,170.7 181,170.44 181.7,170.44 181.83,170.32 181.83,169.62 181.7,169.49 179.8,169.49 179.67,169.62 179.67,171.27 179.8,171.4 180.69,171.4

Small or netless copper shapes (teardrops, artwork), in the pictures only: 20 on TOP, 359 on BOTTOM, 1 on IN1

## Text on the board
Ref Des/Silkscreen Bottom: H10 | SODIMM-only Support DDR3L | H6
User.Comments: LA9981P | Amanda_shi | 2013-05-24 | 2014-05-24 | VBW00 | 1.0(A00)
COMPVAL_TYPE_TOP: Width/space | 4.5/5.5 | 5 / 8 | 4 / 6.5 | 4 / 12 | SB_1_2mm-6L and 8L and 10L(4mil & 5mil 50ohm)_120807 | 100 ohm
COMPVAL_TYPE_BOTTOM: FIGURE | SIZE | 8.0 | 10.0 | 22.0 | 24.0 | 28.0 | 31.0 | 35.0 | 36.0 | 39.0 | 91.0 | 110.0 | 130.0 | 146.0 | 40.0 | 43.0 | 47.0 | 63.0 | 71.0 | 28.0x16.0 | 59.0x24.0 | 63.0x28.0 | 71.0x20.0 | 71.0x31.0 | 79.0x31.0 | 87.0x43.0 | 91.0x35.0 | 94.0x39.0 | 110.0x39.0 | 146.0x126.0 | DRILL CHART: TOP to BOTTOM | ALL UNITS ARE IN MILS | PLATED | NON-PLATED | QTY | 4930 | 719 | 19 | 6 | 25 | 22 | 8 | 4 | 9 | 2 | 1 | 7 | 26
User.22: 183.05 | 174.00 | 104.45 | 88.30 | 55.01 | 16.00 | 1.25 | 103.70 | 58.34 | 24.93 | 4.55 | 168.55 | 173.50
User.25: 2.80 | n | 9.00 | 6.00 | 3.70 | 8.00 | 3.30 | 2.30 | 3.20 | 5.80
User.26: 203.30 | 198.28 | 194.00 | 144.40 | 116.00 | 97.60 | 84.00 | 71.90 | 61.00 | 29.40 | 21.10 | 2.60 | 0.00 | 149.90 | 114.20 | 104.50 | 98.76 | 67.00 | 33.20 | 8.50 | 76.50 | 89.50 | 89.55 | 115.85 | 124.16 | 139.60 | 163.50 | 182.60
User.27: WHITE PAINT
User.28: 217.12 | 214.88 | 212.51 | 209.10 | 213.45 | 179.85 | 155.58 | 158.85 | 131.90 | 69.68 | 14.60 | 0.00 | 1.85 | 3.45 | SCALE | 1.000 | 12.70 | 27.00 | 44.60 | 62.20 | 17.00 | 81.47 | 90.60 | 103.25 | 105.45 | 145.77 | 32.50 | 40.80 | 93.32 | 154.95 | 183.80
User.29: WHITE PAINT
User.30: 0.00
User.31: 217.12 | 214.88 | 212.51 | 209.10 | 213.45 | 179.85 | 155.58 | 158.85 | 131.90 | 69.68 | 14.60 | 0.00 | 1.85 | 3.45 | SCALE | 1.000 | 12.70 | 27.00 | 44.60 | 62.20 | 17.00 | 81.47 | 90.60 | 103.25 | 105.45 | 145.77 | 32.50 | 40.80 | 93.32 | 154.95 | 183.80
User.32: 183.05 | 174.00 | 104.45 | 88.30 | 55.01 | 16.00 | 1.25 | 103.70 | 58.34 | 24.93 | 4.55 | 168.55 | 173.50
User.35: 2.80 | n | 9.00 | 6.00 | 3.70 | 8.00 | 3.30 | 2.30 | 3.20 | 5.80
User.36: 203.30 | 198.28 | 194.00 | 144.40 | 116.00 | 97.60 | 84.00 | 71.90 | 61.00 | 29.40 | 21.10 | 2.60 | 0.00 | 149.90 | 114.20 | 104.50 | 98.76 | 67.00 | 33.20 | 8.50 | 76.50 | 89.50 | 89.55 | 115.85 | 124.16 | 139.60 | 163.50 | 182.60
User.37: WHITE PAINT
User.38: WHITE PAINT
User.39: 0.00
